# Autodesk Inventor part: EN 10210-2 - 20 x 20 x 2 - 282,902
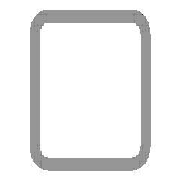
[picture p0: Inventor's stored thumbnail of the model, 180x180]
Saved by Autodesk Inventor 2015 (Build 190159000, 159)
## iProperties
_CCFamilyMember: 1
_CCFamilyDisplayName: DIN EN 10210-2 (Square) - Tube
_FrameMemberDoc: Frame Member File
_Version: 15.0.0
_GetPNFromCC: 1
Created: 2015-05
Part Number: EN 10210-2 - 20 x 20 x 2 - 282,902
Material: Steel, Mild
Description: Tube
Document SubType Name: Modeling
Standard: DIN
Designer: TREINA6
Standard Revision: 1997
Standards Organization: DIN
Language: en-US
Size Designation: 20 x 20 x 2
Categories: <MemberInstance><Categories><Category DisplayName="Structural Shapes" InternalName="089c4875-fa83-4c05-b084-43b9cc11f5ed" Mnemonic="GRDR"><CategoryParameter Dis
Stock Number: 20 x 20 x 2
Density: 7.85 g/cm^3
Appearance: Semi-Polished
IsCustomPart: 1
G_L: 282,902 mm
G_W: 20,000 mm
G_H: 20,000 mm
+AF65A11D-AA21-4BB6-9A7F-682C94FE4538+CUTDETAIL1: Miter 60,00 deg
+45447D7F-895F-4506-8804-617C93922C5F+CUTDETAIL2: Miter 60,00 deg
Author: TREINA6
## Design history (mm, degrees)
node "Start plane"
node "End plane"
sketch "Sketch"
  geometry: L1 (-10, -7)-(-10, 7); L2 (-7, 10)-(7, 10); L3 (10, 7)-(10, -7); L4 (7, -10)-(-7, -10); L5 (-7, 8)-(7, 8); L6 (8, 7)-(8, -7); L7 (7, -8)-(-7, -8); L8 (-8, -7)-(-8, 7); L9 (0, 14.87)-(0, -14.87) reference; L10 (-14.87, 0)-(14.87, 0) reference; A1 r 3 centre (-7, -7) between (-10, -7) and (-7, -10); A2 r 3 centre (-7, 7) between (-7, 10) and (-10, 7); A3 r 3 centre (7, 7) between (10, 7) and (7, 10); A4 r 3 centre (7, -7) between (7, -10) and (10, -7); A5 r 1 centre (-7, 7) between (-7, 8) and (-8, 7); A6 r 1 centre (7, 7) between (8, 7) and (7, 8); A7 r 1 centre (7, -7) between (7, -8) and (8, -7); A8 r 1 centre (-7, -7) between (-8, -7) and (-7, -8)
  constraints: 16 end point, 16 point on circle, 8 centre point, 8 tangent, 4 parallel, 3 equal radius, 2 perpendicular, 7 other
  dimensions: "d7" = 3 radius of A1 (= G_IR); "d10" = 20 distance between parallel lines of L2 L4 (= G_H); "d11" = 20 distance between parallel lines of L1 L3 (= G_W); "d12" = 2 distance between parallel lines of L3 L6 (= G_T); "d15" = 10 distance between parallel lines of L2 L10 (= 0.5 x d10); "d16" = 10 distance between parallel lines of L9 L3 (= 0.5 x d11)
extrude "Body" new body sketch "Sketch" stored distance "d3" = 282.90163 (= G_L); taper "d4" = 0 deg
node "Driven Length"
  sketch "Sketch3"
    geometry: L1 (0, 0)-(10, 0) reference
    constraints: 2 end point, 1 horizontal
  workplane "Work Plane3"
  sketch "Sketch4"
    geometry: L1 (-2, 0)-(12, 0) reference; L2 (-2, 282.902)-(12, 282.902) reference
    dimensions: "d18" = 282.90163 distance between parallel lines of L1 L2 (derived)
workplane "Work Plane4"
split "Split1"
workplane "Work Plane5"
split "Split2"
body "Solid1"
other parameters: "G_W" = 20 [user parameter; used in 1 equation term], "G_H" = 20 [user parameter; used in 1 equation term], "G_T" = 2 [user parameter; used in 1 equation term], "G_IR" = 3 [user parameter; used in 1 equation term], "G_L" = 282.90163 (= d18) [user parameter; used in 1 equation term], "G_OFFSET_START" = 0 [user parameter; used in 1 equation term], "G_OFFSET_END" = 0 [user parameter; used in 1 equation term], "d13" = 0 (computed from G_OFFSET_START), "d14" = 282.90163 (= G_OFFSET_END + B_L), "B_L" = 282.90163 [user parameter; used in 1 equation term], "d17" = 90 deg
